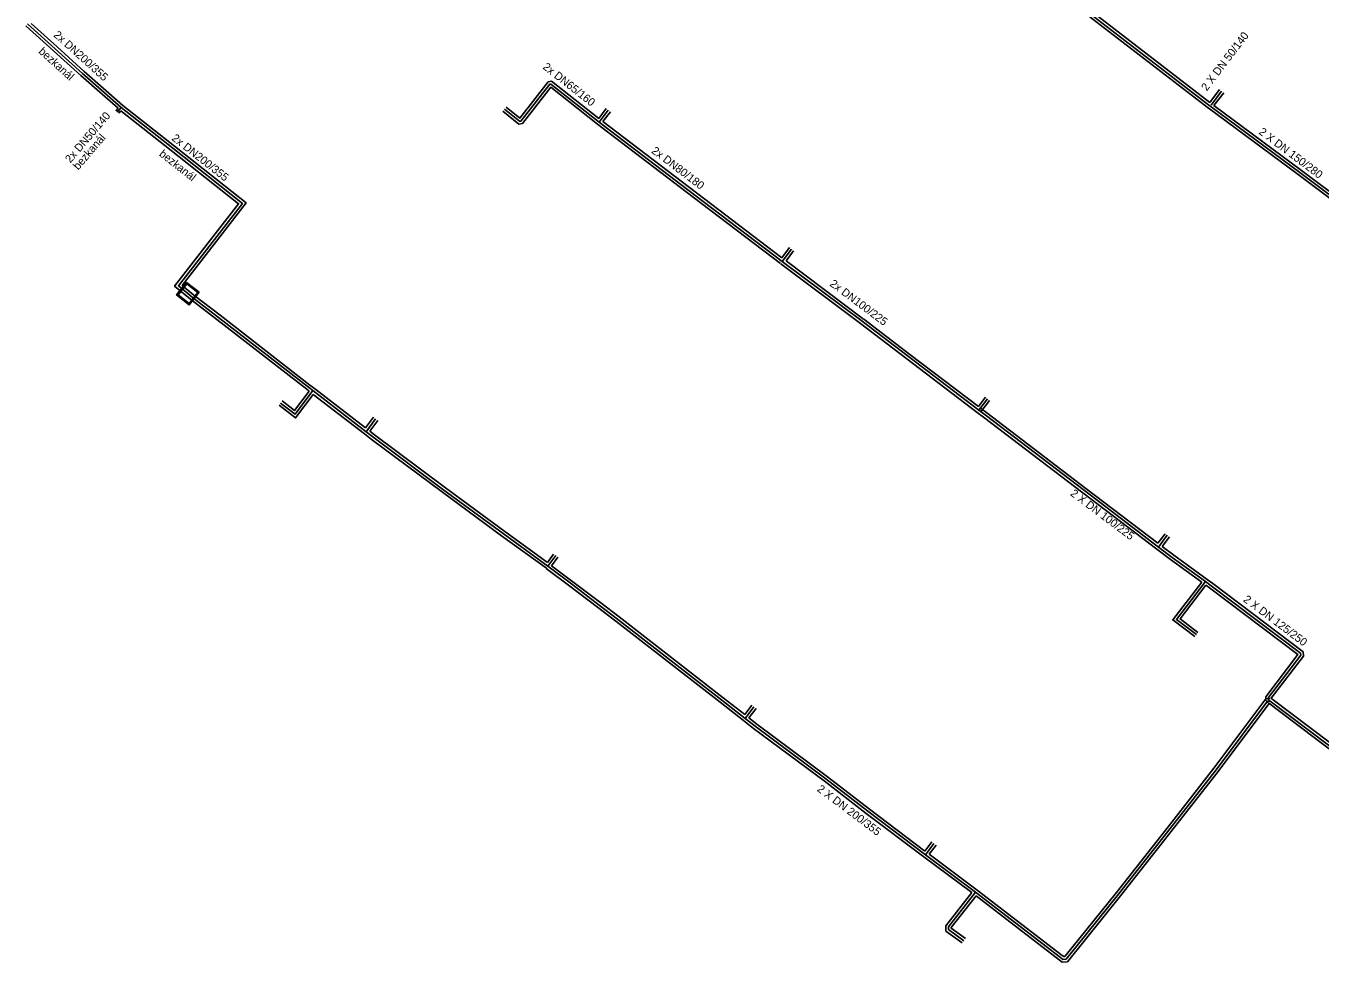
# Model space of a CAD drawing. Extents: x -606118 to -604472, y -1157869 to -1156854.
# Drawn here: x -606025.5 to -605782.8, y -1157718.1 to -1157542.5 of the extents above; entities that cross this region are included whole.
import ezdxf

# ---------------------------------------------------------------- set-up
doc = ezdxf.new("R2010")
doc.units = 0
for name, color, linetype in [('Osa trasy teplovodu', 7, 'Continuous'), ('Teplovod - trasa - okraj', 7, 'Continuous'), ('Teplovod - trasa popis', 7, 'Continuous'), ('Teplovod - trasa popis 2', 7, 'Continuous'), ('Šachta trasy teplovodu', 7, 'Continuous')]:
    doc.layers.add(name, color=color, linetype=linetype)

msp = doc.modelspace()

# ---------------------------------------------------------------- linework, layer by layer
at = {"layer": 'Osa trasy teplovodu'}
for p, q in [((-605803.25, -1157557.32), (-605801.27, -1157554.72)), ((-606007.6, -1157557.8), (-606008.33, -1157558.64)), ((-605917.96, -1157560.52), (-605916.26, -1157558.28)), ((-605883.64, -1157586.68), (-605881.92, -1157584.35)), ((-605868.69, -1157597.87), (-605883.64, -1157586.68)), ((-605961.68, -1157618.59), (-605971.66, -1157610.88)), ((-605846.79, -1157614.56), (-605845.17, -1157612.42)), ((-605961.68, -1157618.59), (-605959.89, -1157616.18)), ((-605813.11, -1157640.21), (-605811.45, -1157638.02)), ((-605927.6, -1157643.81), (-605926.12, -1157641.83)), ((-605890.6, -1157672.35), (-605888.95, -1157670.2)), ((-605847.41, -1157704.94), (-605856.82, -1157697.92)), ((-605856.81, -1157697.91), (-605855.21, -1157695.81))]:
    msp.add_line(p, q, dxfattribs=at)
for points in [[(-605803.26, -1157557.65), (-605803.42, -1157557.53), (-605827.81, -1157538.77)], [(-606007.6, -1157557.8), (-606011.29, -1157554.53), (-606014.85, -1157551.39), (-606019.95, -1157546.8), (-606025.13, -1157542.12)], [(-605917.96, -1157560.52), (-605927.02, -1157553.39), (-605927.24, -1157553.44), (-605932.64, -1157560.34), (-605932.89, -1157560.38), (-605935.73, -1157558.1)], [(-605994.27, -1157593.35), (-605995.09, -1157592.69), (-605996.87, -1157591.23), (-605984.87, -1157575.76), (-605997.94, -1157565.42), (-606007.6, -1157557.8)], [(-605770.65, -1157581.94), (-605786.61, -1157569.98), (-605803.26, -1157557.65)], [(-605883.64, -1157586.68), (-605900.02, -1157574.2), (-605917.18, -1157561.14), (-605917.96, -1157560.52)], [(-605971.66, -1157610.88), (-605972.5, -1157610.23), (-605989.37, -1157597.14), (-605994.27, -1157593.35)], [(-605846.79, -1157614.56), (-605860.01, -1157604.5), (-605868.69, -1157597.87)], [(-605971.66, -1157610.88), (-605974.99, -1157615.3), (-605977.7, -1157613.21)], [(-605813.11, -1157640.21), (-605827.01, -1157629.63), (-605845.62, -1157615.45), (-605846.79, -1157614.56)], [(-605927.59, -1157643.8), (-605935.98, -1157637.69), (-605947.07, -1157629.52), (-605960.41, -1157619.57), (-605961.68, -1157618.59)], [(-605804.3, -1157646.69), (-605810.54, -1157642.17), (-605813.11, -1157640.21)], [(-605890.6, -1157672.35), (-605895, -1157668.91), (-605914.52, -1157653.72), (-605917.99, -1157651.09), (-605923.19, -1157647.13), (-605927.6, -1157643.81)], [(-605804.3, -1157646.69), (-605809.74, -1157653.79), (-605806.01, -1157656.62)], [(-605792.14, -1157669.09), (-605792.49, -1157668.78), (-605792.49, -1157668.46), (-605786.44, -1157660.51), (-605786.48, -1157660.12), (-605803.22, -1157647.48), (-605804.3, -1157646.69)], [(-605792.14, -1157669.09), (-605792.69, -1157669.15), (-605802.31, -1157682), (-605810.23, -1157692.14), (-605820.6, -1157705.32), (-605830.42, -1157717.5), (-605831.02, -1157717.54), (-605831.46, -1157717.21)], [(-605768.35, -1157686.97), (-605769.16, -1157686.36), (-605777.67, -1157680.04), (-605792.14, -1157669.09)], [(-605856.81, -1157697.91), (-605867.58, -1157689.78), (-605875.48, -1157683.68), (-605888.71, -1157673.82), (-605890.6, -1157672.35)], [(-605847.41, -1157704.94), (-605852.45, -1157711.42), (-605852.45, -1157711.97), (-605849.61, -1157714.06)], [(-605831.46, -1157717.21), (-605839.05, -1157711.38), (-605847.41, -1157704.94)]]:
    msp.add_lwpolyline(points, dxfattribs=at)
at = {"layer": 'Teplovod - trasa - okraj'}
for p, q in [((-605827.5, -1157538.37), (-605803.51, -1157556.83)), ((-605803.51, -1157556.83), (-605801.67, -1157554.41)), ((-605800.88, -1157555.02), (-605802.71, -1157557.43)), ((-606008.59, -1157558.41), (-606008.19, -1157557.94)), ((-606007.65, -1157558.39), (-606008.06, -1157558.87)), ((-605918.05, -1157559.82), (-605916.66, -1157557.98)), ((-605915.86, -1157558.59), (-605917.27, -1157560.44)), ((-605883.74, -1157585.97), (-605882.32, -1157584.06)), ((-605881.52, -1157584.65), (-605882.94, -1157586.57)), ((-605868.98, -1157598.27), (-605883.94, -1157587.08)), ((-605882.94, -1157586.57), (-605868.39, -1157597.47)), ((-605971.35, -1157610.49), (-605961.78, -1157617.88)), ((-605961.99, -1157618.99), (-605971.57, -1157611.59)), ((-605846.88, -1157613.86), (-605845.56, -1157612.12)), ((-605844.77, -1157612.72), (-605846.39, -1157614.86)), ((-605961.78, -1157617.88), (-605960.29, -1157615.89)), ((-605959.49, -1157616.48), (-605960.99, -1157618.5)), ((-605813.21, -1157639.5), (-605811.85, -1157637.71)), ((-605811.05, -1157638.32), (-605812.41, -1157640.11)), ((-605927.69, -1157643.1), (-605926.52, -1157641.53)), ((-605925.71, -1157642.13), (-605926.9, -1157643.71)), ((-605890.69, -1157671.64), (-605889.35, -1157669.89)), ((-605888.55, -1157670.5), (-605889.9, -1157672.26)), ((-605856.91, -1157697.22), (-605855.61, -1157695.51)), ((-605854.81, -1157696.12), (-605856.11, -1157697.82)), ((-605856.11, -1157697.82), (-605847.11, -1157704.54)), ((-605848.12, -1157705.03), (-605857.12, -1157698.32))]:
    msp.add_line(p, q, dxfattribs=at)
for points in [[(-605803.56, -1157558.05), (-605803.72, -1157557.93), (-605828.11, -1157539.16)], [(-606008.19, -1157557.94), (-606011.62, -1157554.91), (-606015.19, -1157551.77), (-606020.28, -1157547.17), (-606025.46, -1157542.49)], [(-606024.49, -1157542.02), (-606019.61, -1157546.43), (-606014.52, -1157551.02), (-606010.96, -1157554.16), (-606007.27, -1157557.42)], [(-605918.27, -1157560.92), (-605927.05, -1157554), (-605932.37, -1157560.81), (-605933.03, -1157560.91), (-605936.05, -1157558.49)], [(-605935.42, -1157557.71), (-605932.83, -1157559.78), (-605927.53, -1157552.99), (-605926.9, -1157552.85), (-605918.05, -1157559.82)], [(-606007.29, -1157557.4), (-605997.63, -1157565.03), (-605984.17, -1157575.68), (-605996.18, -1157591.15), (-605993.95, -1157592.96)], [(-605994.59, -1157593.74), (-605997.57, -1157591.31), (-605985.57, -1157575.85), (-605998.25, -1157565.82), (-606007.65, -1157558.39)], [(-605770.95, -1157582.34), (-605786.91, -1157570.38), (-605803.56, -1157558.05)], [(-605802.71, -1157557.43), (-605786.31, -1157569.58), (-605769.7, -1157582.03)], [(-605883.95, -1157587.07), (-605900.33, -1157574.6), (-605917.49, -1157561.53), (-605918.27, -1157560.92)], [(-605917.27, -1157560.44), (-605899.72, -1157573.8), (-605883.74, -1157585.97)], [(-605972.36, -1157610.98), (-605972.81, -1157610.63), (-605989.68, -1157597.53), (-605994.58, -1157593.75)], [(-605993.96, -1157592.95), (-605989.06, -1157596.74), (-605972.2, -1157609.84), (-605971.35, -1157610.49)], [(-605847.09, -1157614.96), (-605860.32, -1157604.9), (-605868.99, -1157598.27)], [(-605868.38, -1157597.47), (-605859.71, -1157604.1), (-605846.88, -1157613.86)], [(-605971.57, -1157611.59), (-605974.9, -1157616), (-605978, -1157613.6)], [(-605977.39, -1157612.81), (-605975.09, -1157614.59), (-605972.36, -1157610.98)], [(-605813.42, -1157640.6), (-605827.31, -1157630.03), (-605845.92, -1157615.85), (-605847.09, -1157614.96)], [(-605846.48, -1157614.16), (-605845.32, -1157615.05), (-605826.7, -1157629.24), (-605813.21, -1157639.5)], [(-605927.88, -1157644.2), (-605936.27, -1157638.1), (-605947.36, -1157629.92), (-605960.72, -1157619.97), (-605961.99, -1157618.99)], [(-605960.99, -1157618.5), (-605960.11, -1157619.17), (-605946.77, -1157629.12), (-605935.68, -1157637.29), (-605927.69, -1157643.1)], [(-605805.01, -1157646.8), (-605810.83, -1157642.57), (-605813.42, -1157640.6)], [(-605812.41, -1157640.11), (-605810.24, -1157641.77), (-605804.01, -1157646.29)], [(-605890.91, -1157672.74), (-605895.31, -1157669.3), (-605914.83, -1157654.12), (-605918.3, -1157651.49), (-605923.49, -1157647.53), (-605927.9, -1157644.21)], [(-605926.9, -1157643.71), (-605922.89, -1157646.73), (-605917.69, -1157650.69), (-605914.22, -1157653.33), (-605894.7, -1157668.52), (-605890.69, -1157671.64)], [(-605806.31, -1157657.02), (-605810.44, -1157653.88), (-605805.01, -1157646.8)], [(-605804.01, -1157646.29), (-605802.92, -1157647.08), (-605786.01, -1157659.85), (-605785.92, -1157660.65), (-605791.96, -1157668.58), (-605791.81, -1157668.72)], [(-605804.2, -1157647.39), (-605809.04, -1157653.69), (-605805.7, -1157656.22)], [(-605792.47, -1157669.47), (-605792.99, -1157669), (-605792.99, -1157668.29), (-605786.97, -1157660.38), (-605803.52, -1157647.88), (-605804.2, -1157647.39)], [(-605831.15, -1157716.81), (-605830.87, -1157717.03), (-605830.67, -1157717.02), (-605820.99, -1157705.01), (-605810.63, -1157691.83), (-605802.71, -1157681.7), (-605792.95, -1157668.67), (-605792.19, -1157668.6)], [(-605791.84, -1157668.7), (-605777.37, -1157679.64), (-605768.87, -1157685.96), (-605768.05, -1157686.57)], [(-605792.09, -1157669.59), (-605792.42, -1157669.63), (-605801.92, -1157682.31), (-605809.84, -1157692.44), (-605820.21, -1157705.63), (-605830.17, -1157717.98), (-605831.17, -1157718.06), (-605831.76, -1157717.6)], [(-605769.04, -1157687.08), (-605769.46, -1157686.76), (-605777.97, -1157680.44), (-605792.44, -1157669.49)], [(-605857.12, -1157698.31), (-605867.89, -1157690.18), (-605875.78, -1157684.08), (-605889.02, -1157674.22), (-605890.91, -1157672.74)], [(-605889.9, -1157672.26), (-605888.41, -1157673.43), (-605875.18, -1157683.28), (-605867.28, -1157689.38), (-605856.91, -1157697.22)], [(-605849.9, -1157714.46), (-605852.95, -1157712.23), (-605852.95, -1157711.25), (-605848.12, -1157705.03)], [(-605847.11, -1157704.54), (-605838.74, -1157710.98), (-605831.15, -1157716.81)], [(-605847.32, -1157705.64), (-605851.95, -1157711.59), (-605851.95, -1157711.72), (-605849.31, -1157713.65)], [(-605831.76, -1157717.6), (-605839.35, -1157711.77), (-605847.32, -1157705.64)]]:
    msp.add_lwpolyline(points, dxfattribs=at)
at = {"layer": 'Šachta trasy teplovodu'}
for points in [[(-605992.98, -1157592.43), (-605994.83, -1157594.8), (-605997.2, -1157592.94), (-605995.34, -1157590.58), (-605992.98, -1157592.43)], [(-605995.31, -1157590.84), (-605996.94, -1157592.91), (-605994.87, -1157594.53), (-605993.24, -1157592.47), (-605995.31, -1157590.84)]]:
    msp.add_lwpolyline(points, dxfattribs=at)

# ---------------------------------------------------------------- texts
at = {"layer": 'Teplovod - trasa popis'}
for s, rotation, p in [('2x DN200/355', 317.9104, (-606020.39, -1157544.35)), ('2 X DN 50/140', 52.7512, (-605804.05, -1157554.8)), ('2x DN65/160', 321.7696, (-605928.67, -1157550.42)), ('2x DN50/140', 49.3901, (-606017.13, -1157568.29)), ('2 X DN 150/280', 323, (-605794.43, -1157562.63)), ('2x DN200/355', 321.7127, (-605998.25, -1157563.78)), ('2x DN80/180', 322.7108, (-605908.3, -1157566.17)), ('2x DN100/225', 323.1879, (-605874.87, -1157591.11)), ('2 X DN 100/225', 323, (-605829.76, -1157630.42)), ('2 X DN 125/250', 323, (-605797.33, -1157650.31)), ('2 X DN 200/355', 323, (-605877.25, -1157685.86))]:
    msp.add_text(s, height=1.5, rotation=rotation, dxfattribs=at).set_placement(p)
at = {"layer": 'Teplovod - trasa popis 2'}
for rotation, p in [(317.9104, (-606023.21, -1157547.45)), (49.3901, (-606015.64, -1157569.61)), (321.7127, (-606000.6, -1157566.73))]:
    msp.add_text('bezkanál', height=1.5, rotation=rotation, dxfattribs=at).set_placement(p)

doc.saveas('drawing.dxf')
